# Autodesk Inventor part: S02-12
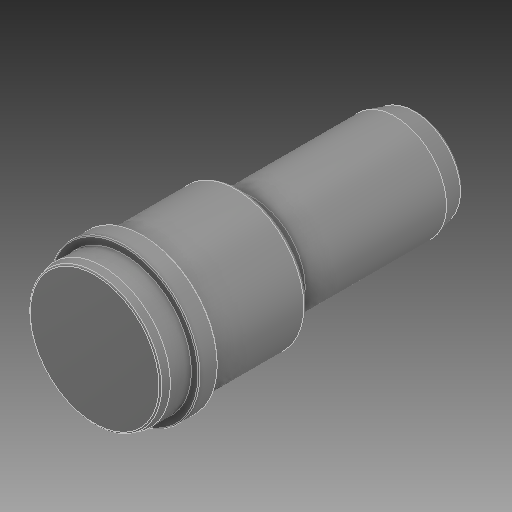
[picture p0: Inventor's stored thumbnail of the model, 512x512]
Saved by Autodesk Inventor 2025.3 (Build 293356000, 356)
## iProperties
Created: 2025-04
Part Number: S02-12
Material: Všeobecné
Document SubType Name: Modeling
Designer: Patrik
Density: 1 g/cm^3
Appearance: Výchozí
Stock Number: E 1002 DLC/32-36/55
Description: Vodící kolík s nákružkem
User Status: 1.7131
Author: Patrik
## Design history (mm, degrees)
feature "Base1"
node "Těleso1"
